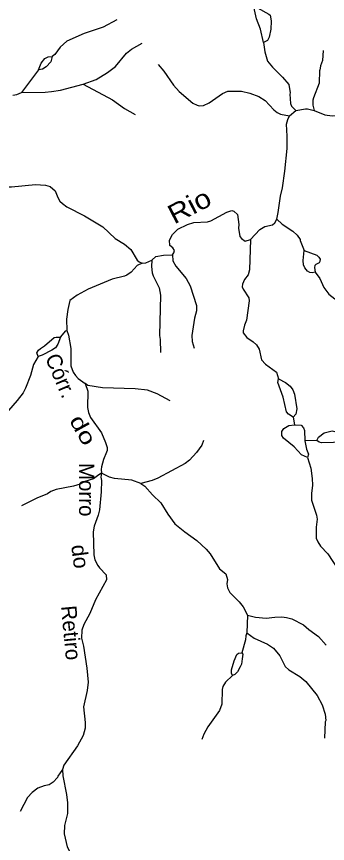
# Model space of a CAD drawing. Extents: x 346.5 to 372.4, y 7400.3 to 7428.2.
# Drawn here: x 367.524 to 369.144, y 7415.59 to 7419.897 of the extents above; entities that cross this region are included whole.
import ezdxf
from ezdxf.enums import TextEntityAlignment as Align

# ---------------------------------------------------------------- set-up
doc = ezdxf.new("R2010")
doc.units = 0
doc.header["$LTSCALE"] = 0.032
doc.layers.add('2', color=7, linetype='Continuous', lineweight=25)
doc.layers.add('7', color=7, linetype='Continuous', lineweight=25)
doc.layers.add('61', color=7, linetype='Continuous')

msp = doc.modelspace()

# ---------------------------------------------------------------- linework, layer by layer
at = {"layer": '2'}
for points in [[(368.7598, 7419.9469), (368.7795, 7419.9432), (368.8382, 7419.9098), (368.8448, 7419.904), (368.848, 7419.8954), (368.851, 7419.873), (368.8486, 7419.8313), (368.8401, 7419.789), (368.8315, 7419.7723), (368.8106, 7419.7627), (368.7947, 7419.8318), (368.7742, 7419.8858)], [(367.6385, 7419.6201), (367.6532, 7419.655), (367.6716, 7419.6794), (367.6897, 7419.687), (367.7104, 7419.6886), (367.702, 7419.6612), (367.6778, 7419.6354), (367.6595, 7419.6237)], [(369.0222, 7418.679), (369.0886, 7418.654), (369.0989, 7418.6444), (369.1059, 7418.6336), (369.1034, 7418.6217), (369.0999, 7418.6152), (369.0839, 7418.6065), (369.0787, 7418.5997), (369.0769, 7418.5901), (369.08, 7418.5663), (369.0641, 7418.5627), (369.0525, 7418.5643), (369.0404, 7418.5715), (369.0264, 7418.5879), (369.0184, 7418.6039), (369.0169, 7418.6266)], [(367.6362, 7418.1272), (367.6307, 7418.1454), (367.638, 7418.1593), (367.6497, 7418.1683), (367.6705, 7418.1818), (367.7206, 7418.225), (367.7299, 7418.2279), (367.7532, 7418.2278), (367.7397, 7418.1904), (367.7268, 7418.1725), (367.7085, 7418.1592), (367.6574, 7418.133)], [(368.8887, 7418.0102), (368.9251, 7417.9904), (368.949, 7417.9719), (368.963, 7417.9533), (368.9728, 7417.9302), (368.9849, 7417.854), (368.9797, 7417.8264), (368.9661, 7417.81), (368.9406, 7417.8257), (368.931, 7417.8388), (368.9132, 7417.9156), (368.8848, 7417.9919)], [(368.9724, 7417.7706), (369.0066, 7417.7684), (369.0191, 7417.755), (369.0236, 7417.741), (369.0269, 7417.6865), (369.0353, 7417.6438), (369.045, 7417.6183), (369.0402, 7417.6004), (369.0087, 7417.6141), (368.9707, 7417.6555), (368.9157, 7417.7018), (368.9059, 7417.7147), (368.9054, 7417.7367), (368.9159, 7417.7519), (368.9432, 7417.7671)], [(369.0877, 7417.6894), (369.0973, 7417.706), (369.1263, 7417.7289), (369.1677, 7417.74), (369.2103, 7417.7296), (369.2278, 7417.7119), (369.2172, 7417.6957), (369.2063, 7417.6863), (369.1752, 7417.6779), (369.1129, 7417.6775), (369.1013, 7417.6802)], [(368.649, 7416.4648), (368.6436, 7416.4781), (368.644, 7416.4943), (368.6571, 7416.5421), (368.6721, 7416.574), (368.6811, 7416.5819), (368.6984, 7416.5834), (368.7026, 7416.5764), (368.6996, 7416.5521), (368.6953, 7416.5246), (368.6889, 7416.5097), (368.6759, 7416.4845), (368.6618, 7416.4698)]]:
    msp.add_lwpolyline(points, close=True, dxfattribs=at)
at = {"layer": '7'}
for p, q in [((367.6385, 7419.6201), (367.5502, 7419.5017)), ((368.9661, 7417.81), (368.9724, 7417.7706)), ((369.0877, 7417.6894), (369.0269, 7417.6865))]:
    msp.add_line(p, q, dxfattribs=at)
for points in [[(368.0474, 7419.8808), (367.9749, 7419.8417), (367.876, 7419.809), (367.7868, 7419.7684), (367.7509, 7419.7373), (367.7228, 7419.6997), (367.7104, 7419.6886)], [(367.8712, 7419.5451), (367.9382, 7419.5699), (367.9972, 7419.605), (368.0394, 7419.6369), (368.0968, 7419.707), (368.1231, 7419.7269), (368.1781, 7419.7588)], [(368.8106, 7419.7627), (368.8172, 7419.7126), (368.8323, 7419.6648), (368.8571, 7419.6329), (368.9097, 7419.5819), (368.9423, 7419.5428), (368.9503, 7419.4998), (368.9471, 7419.4926), (368.9519, 7419.4448), (368.9567, 7419.4305), (368.9791, 7419.4075)], [(369.1209, 7419.7198), (369.1177, 7419.668), (369.1085, 7419.6409), (369.1049, 7419.6186), (369.1017, 7419.6162), (369.1009, 7419.55), (369.0706, 7419.4735), (369.0682, 7419.4608), (369.0682, 7419.4353), (369.0753, 7419.4072)], [(368.2618, 7419.648), (368.292, 7419.6122), (368.3422, 7419.5405), (368.3717, 7419.507), (368.4419, 7419.4456), (368.4658, 7419.4352), (368.4761, 7419.4321), (368.4977, 7419.4337), (368.5279, 7419.448), (368.5965, 7419.4966), (368.6252, 7419.5086), (368.6969, 7419.5086), (368.7399, 7419.4982), (368.7861, 7419.4807), (368.8188, 7419.4592), (368.865, 7419.4105), (368.8818, 7419.397), (368.8993, 7419.389), (368.9454, 7419.3807)], [(367.5502, 7419.5017), (367.6736, 7419.503), (367.7055, 7419.507), (367.7533, 7419.5141), (367.8712, 7419.5451)], [(367.8712, 7419.5451), (368.0235, 7419.4639), (368.0864, 7419.4185), (368.143, 7419.3867)], [(367.5053, 7419.4872), (367.5253, 7419.4914), (367.5502, 7419.5017)], [(368.9791, 7419.4075), (369.03, 7419.4161), (369.0404, 7419.4161), (369.0753, 7419.4072)], [(368.8794, 7418.8422), (368.8873, 7418.8758), (368.8985, 7418.9619), (368.9089, 7419.0049), (368.9216, 7419.091), (368.9336, 7419.2105), (368.9344, 7419.2743), (368.9312, 7419.3364), (368.9375, 7419.3603), (368.9454, 7419.3807), (368.9791, 7419.4075)], [(369.0753, 7419.4072), (369.1304, 7419.3858), (369.1687, 7419.3803), (369.3679, 7419.3842), (369.3909, 7419.3769), (369.4157, 7419.3569)], [(367.4431, 7419.026), (367.4792, 7419.0105), (367.4983, 7419.0097), (367.6226, 7419.0224), (367.6752, 7419.0184), (367.6991, 7419.0121), (367.7246, 7418.9898), (367.7397, 7418.9539), (367.7501, 7418.9364), (367.7636, 7418.9228), (367.7868, 7418.9053), (367.8776, 7418.8591), (367.9733, 7418.8017), (368.0386, 7418.7403), (368.0864, 7418.7116), (368.1199, 7418.6845), (368.1533, 7418.6283), (368.1629, 7418.6194), (368.1787, 7418.6125)], [(368.3371, 7418.6561), (368.3439, 7418.6657), (368.3467, 7418.6781), (368.3378, 7418.6919), (368.3231, 7418.7045), (368.3207, 7418.7331), (368.3358, 7418.7626), (368.3638, 7418.7889), (368.414, 7418.8136), (368.4482, 7418.8248), (368.5184, 7418.828), (368.5359, 7418.8328), (368.6196, 7418.879), (368.6451, 7418.8869), (368.6554, 7418.8838), (368.6746, 7418.8654), (368.6817, 7418.8137), (368.6801, 7418.7945), (368.6873, 7418.7523), (368.6969, 7418.7403), (368.7144, 7418.7276), (368.7425, 7418.7357)], [(368.7425, 7418.7357), (368.7909, 7418.7881), (368.818, 7418.8033), (368.8571, 7418.8128), (368.8705, 7418.8222), (368.8794, 7418.8422)], [(368.8794, 7418.8422), (368.9081, 7418.816), (368.963, 7418.7793), (368.9854, 7418.7579), (369.0013, 7418.7363), (369.0013, 7418.73), (369.0222, 7418.679)], [(368.7425, 7418.7357), (368.7383, 7418.5778), (368.7303, 7418.5522), (368.7112, 7418.5283), (368.7009, 7418.5028), (368.7001, 7418.4901), (368.7048, 7418.4773), (368.7351, 7418.4319), (368.7359, 7418.4168), (368.7224, 7418.3164), (368.7112, 7418.2893), (368.7048, 7418.2606), (368.7056, 7418.2494), (368.7232, 7418.2247), (368.7566, 7418.2032), (368.7742, 7418.1873), (368.7877, 7418.1649), (368.8005, 7418.1099), (368.8204, 7418.0868), (368.8786, 7418.0446), (368.8887, 7418.0102)], [(368.2298, 7418.6291), (368.2502, 7418.6481), (368.2889, 7418.6542), (368.3371, 7418.6561)], [(368.3371, 7418.6561), (368.339, 7418.6256), (368.3534, 7418.5969), (368.4076, 7418.5331), (368.4283, 7418.4949), (368.461, 7418.3929), (368.461, 7418.3642), (368.4514, 7418.3259), (368.4371, 7418.2367), (368.4387, 7418.204), (368.4498, 7418.1705)], [(368.1787, 7418.6125), (368.1532, 7418.6012), (368.1207, 7418.5666), (368.0992, 7418.5506), (368.0864, 7418.5443), (368.0227, 7418.5291), (367.8968, 7418.4765), (367.8402, 7418.4462), (367.8011, 7418.4176), (367.7907, 7418.3721), (367.7844, 7418.3211), (367.787, 7418.2617)], [(368.1787, 7418.6125), (368.198, 7418.6136), (368.2298, 7418.6291)], [(368.2298, 7418.6291), (368.2275, 7418.5953), (368.2315, 7418.5618), (368.2362, 7418.5467), (368.2673, 7418.4837), (368.2737, 7418.4455), (368.2697, 7418.2367), (368.2729, 7418.2143), (368.2745, 7418.1466)], [(369.08, 7418.5663), (369.1041, 7418.5331), (369.1256, 7418.4853), (369.1511, 7418.4518), (369.1822, 7418.4271), (369.2779, 7418.3817), (369.332, 7418.3474), (369.3695, 7418.31), (369.391, 7418.2709)], [(367.7532, 7418.2278), (367.7804, 7418.2602), (367.787, 7418.2617)], [(367.787, 7418.2617), (367.7945, 7418.2376), (367.8075, 7418.1681), (367.8067, 7418.0773), (367.8194, 7418.0454), (367.8306, 7418.0278), (367.8449, 7418.0127), (367.8825, 7417.9853)], [(367.6362, 7418.1272), (367.613, 7418.0852), (367.5963, 7418.0279), (367.5716, 7417.9609), (367.5588, 7417.9378), (367.5278, 7417.8979), (367.4815, 7417.8454), (367.4584, 7417.7983), (367.4536, 7417.7776), (367.4536, 7417.7441), (367.4588, 7417.6867), (367.4345, 7417.5752), (367.4273, 7417.4828), (367.4266, 7417.474)], [(367.8825, 7417.9853), (367.8951, 7417.9466), (367.8936, 7417.8605), (367.8983, 7417.835), (367.9095, 7417.8095), (367.9669, 7417.7298), (367.9884, 7417.6788), (367.9956, 7417.6533), (367.9964, 7417.6366), (367.9924, 7417.6278), (367.9764, 7417.5895), (367.9669, 7417.5513), (367.9645, 7417.5385), (367.9669, 7417.5182)], [(368.3247, 7417.8964), (368.257, 7417.9314), (368.206, 7417.9505), (368.1422, 7417.9585), (367.9717, 7417.9625), (367.8962, 7417.9758), (367.8825, 7417.9853)], [(368.4977, 7417.6892), (368.4889, 7417.6645), (368.4618, 7417.627), (368.4251, 7417.5871), (368.402, 7417.5696), (368.2602, 7417.4931), (368.2315, 7417.4803), (368.1715, 7417.4655)], [(369.0402, 7417.6004), (369.0571, 7417.5449), (369.0651, 7417.4907), (369.0659, 7417.4572), (369.0603, 7417.4126), (369.0603, 7417.3791), (369.0874, 7417.301), (369.0906, 7417.2787), (369.0858, 7417.2373), (369.0858, 7417.1799), (369.0937, 7417.1608), (369.1081, 7417.1385), (369.1455, 7417.0986), (369.2021, 7417.0141), (369.2364, 7416.936), (369.2579, 7416.8468), (369.2579, 7416.8093), (369.2643, 7416.7591), (369.2994, 7416.6396), (369.301, 7416.6356)], [(367.9669, 7417.5182), (367.9524, 7417.511), (367.9245, 7417.49), (367.8805, 7417.4755), (367.8557, 7417.4617), (367.8202, 7417.4517), (367.731, 7417.4341), (367.7031, 7417.4238), (367.6848, 7417.4118), (367.6306, 7417.3895), (367.5501, 7417.3489)], [(367.9669, 7417.5182), (367.9631, 7417.4973), (367.9661, 7417.4805), (367.9645, 7417.4222), (367.9557, 7417.3281), (367.9493, 7417.2995), (367.9294, 7417.2421), (367.9238, 7417.2134), (367.927, 7417.0938), (367.9326, 7417.0667), (367.9469, 7417.0381), (367.9557, 7417.0253), (367.9908, 7416.9894), (367.9924, 7416.9631), (367.9358, 7416.8595), (367.9063, 7416.7878), (367.8744, 7416.7304), (367.8649, 7416.7017), (367.8633, 7416.6603), (367.8728, 7416.6173), (367.8904, 7416.5025), (367.8967, 7416.4308), (367.892, 7416.3877), (367.8728, 7416.3017), (367.8824, 7416.2204), (367.8816, 7416.1917), (367.8704, 7416.1534), (367.8417, 7416.0993), (367.77, 7415.9988), (367.7635, 7415.9752)], [(368.1715, 7417.4655), (368.1247, 7417.4819), (368.0338, 7417.4907), (368.0083, 7417.4979), (367.9669, 7417.5182)], [(368.1715, 7417.4655), (368.1932, 7417.4517), (368.2323, 7417.4054), (368.2753, 7417.3648), (368.3119, 7417.3058), (368.3486, 7417.2556), (368.4004, 7417.2134), (368.4642, 7417.1687), (368.5128, 7417.1225), (368.5335, 7417.0986), (368.5813, 7417.0213), (368.614, 7416.9942), (368.6228, 7416.9647), (368.6204, 7416.9424), (368.6235, 7416.9217), (368.6355, 7416.897), (368.6833, 7416.8484), (368.704, 7416.8229), (368.728, 7416.7786), (368.7236, 7416.687)], [(368.728, 7416.7786), (368.7686, 7416.7695), (368.8244, 7416.7639), (368.869, 7416.7695), (368.9057, 7416.7703), (368.9312, 7416.7679), (368.9575, 7416.7599), (369.0188, 7416.7288), (369.0467, 7416.7041), (369.0969, 7416.6683), (369.1376, 7416.6228)], [(368.7236, 7416.687), (368.7183, 7416.6718), (368.7168, 7416.6507), (368.6984, 7416.5834)], [(368.7236, 7416.687), (368.7614, 7416.6595), (368.8308, 7416.6276), (368.8634, 7416.6077), (368.8953, 7416.5679), (368.924, 7416.5121), (368.9431, 7416.4945), (368.9997, 7416.4595), (369.0308, 7416.434), (369.0906, 7416.3607), (369.1161, 7416.3128), (369.1312, 7416.2634), (369.1352, 7416.23), (369.132, 7416.2236), (369.1288, 7416.1383)], [(368.649, 7416.4648), (368.6132, 7416.43), (368.5996, 7416.4085), (368.5949, 7416.3925), (368.5933, 7416.316), (368.5821, 7416.2825), (368.5207, 7416.1981), (368.5, 7416.1598), (368.4897, 7416.1319)], [(367.7635, 7415.9752), (367.7389, 7415.9407), (367.7373, 7415.9343), (367.715, 7415.9104), (367.6935, 7415.896), (367.6672, 7415.8904), (367.6354, 7415.8777), (367.6051, 7415.8554), (367.582, 7415.8291), (367.5429, 7415.7574)], [(367.7635, 7415.9752), (367.7652, 7415.9431), (367.7852, 7415.8458), (367.7899, 7415.8012), (367.79, 7415.747), (367.7748, 7415.6848), (367.7716, 7415.6402), (367.7884, 7415.5733), (367.8026, 7415.5476)]]:
    msp.add_lwpolyline(points, dxfattribs=at)

# ---------------------------------------------------------------- texts
at = {"layer": '61'}
for s, height, rotation, width, p in [('Rio', 0.1, 27.412, 1.15, (368.4476, 7418.8664)), ('do', 0.08, 299.025, 1.35, (367.8358, 7417.7243)), ('do', 0.08, 277.524, 1.05, (367.8166, 7417.0799))]:
    msp.add_text(s, height=height, rotation=rotation, dxfattribs=dict(at, width=width)).set_placement(p, align=Align.CENTER)
for s, rotation, p in [('Córr.', 293.056, (367.718, 7418.0114)), ('Morro', 270, (367.8499, 7417.433)), ('Retiro', 275.365, (367.7689, 7416.684))]:
    msp.add_text(s, height=0.08, rotation=rotation, dxfattribs=at).set_placement(p, align=Align.CENTER)

doc.saveas('drawing.dxf')
